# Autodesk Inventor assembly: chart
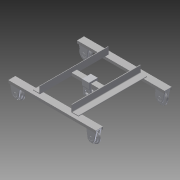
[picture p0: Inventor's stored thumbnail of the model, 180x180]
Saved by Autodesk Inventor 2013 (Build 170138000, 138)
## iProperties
Created: 2009-11
Part Number: chart
Document SubType Name: Assembly
Designer: pokornp
Mass: 486181 g
Surface Area: 105082 cm^2
Volume: 115860 cm^3
Density: 4.19629 g/cm^3
_SolveAssemblyDoc: Frame Generator Solve Assembly
_Version: 15.0.0
Author: pokornp
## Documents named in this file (5)
- C:\Users\boganb\Documents\B2 Design\Goodyear\2013 Tutorial Files\Frame Analysis 1\chart.iam
- C:\Users\boganb\Documents\B2 Design\Goodyear\2013 Tutorial Files\Frame Analysis 1\frame.ipt
- C:\Users\boganb\Documents\B2 Design\Goodyear\2013 Tutorial Files\Frame Analysis 1\side1.iam
- C:\Users\boganb\Documents\B2 Design\Goodyear\2013 Tutorial Files\Frame Analysis 1\Assembly2\Frame\Frame0001.iam
- C:\Users\boganb\Documents\B2 Design\Goodyear\2013 Tutorial Files\Frame Analysis 1\Part12.ipt
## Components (5 placed, 4 different names)
1. frame:1
2. side1:1 [sub-assembly] — Flush:6, Mate:6, Flush:8, Flush:9, Flush:10
3. side1:2 [sub-assembly] — Flush:6, Mate:6, Mate:7, Flush:9
4. Frame0001:1 [sub-assembly] — Flush:4, Mate:4, Mate:5, Flush:5, Mate:7, Flush:8, Flush:10
5. Part12:1 — Flush:4, Mate:4, Mate:5, Flush:5
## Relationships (10: Flush 6, Mate 4)
- Flush:4: Frame0001:1 ↔ Part12:1
- Mate:4: Frame0001:1 ↔ Part12:1
- Mate:5: Frame0001:1 ↔ Part12:1
- Flush:5: Frame0001:1 ↔ Part12:1
- Flush:6: side1:1 ↔ side1:2
- Mate:6: side1:1 ↔ side1:2
- Mate:7: side1:2 ↔ Frame0001:1
- Flush:8: side1:1 ↔ Frame0001:1
- Flush:9: side1:1 ↔ side1:2
- Flush:10: side1:1 ↔ Frame0001:1
